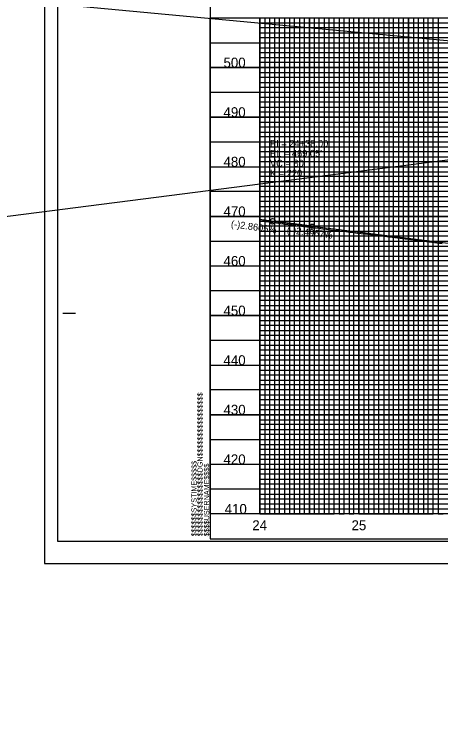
# Model space of a CAD drawing. Extents: x 571503 to 593215, y -77195 to -51828.
# Drawn here: x 581475 to 581905, y -53851 to -53130 of the extents above; entities that cross this region are included whole.
import ezdxf

# ---------------------------------------------------------------- set-up
doc = ezdxf.new("R2010")
doc.units = 0
for name, color, linetype in [('Default', 7, 'Continuous'), ('Exist Vertical Profile Ground Line', 7, 'Continuous'), ('Exist Vertical Profile Horizontal Axis Label Major', 7, 'Continuous'), ('Exist Vertical Profile Vertical Axis Label', 7, 'Continuous'), ('Prop PFL Text', 7, 'Continuous'), ('Prop Vertical Profile Curve Label', 7, 'Continuous'), ('Prop Vertical Profile Grade', 7, 'Continuous'), ('Prop Vertical Profile Grade Label', 7, 'Continuous'), ('Prop VPI Label', 7, 'Continuous'), ('Sheet Clip Boundary CELL', 7, 'Continuous'), ('Sheet DOT Grid CELL', 7, 'Continuous'), ('Sheet Plot Border Inside CELL', 7, 'Continuous'), ('Sheet Plot Border Outside CELL', 7, 'Continuous'), ('Sheet Profile CELL', 7, 'Continuous'), ('Sheet Profile Grid Major CELL', 7, 'Continuous'), ('Sheet Profile Grid Middle CELL', 7, 'Continuous'), ('Sheet Profile Grid Minor CELL', 7, 'Continuous')]:
    doc.layers.add(name, color=color, linetype=linetype)

msp = doc.modelspace()

# ---------------------------------------------------------------- linework, layer by layer
at = {"layer": 'Default'}
msp.add_line((581722.51, -53633.7), (581672.51, -53633.7), dxfattribs=at)
at = {"layer": 'Exist Vertical Profile Ground Line'}
msp.add_lwpolyline([(581722.51, -53338.07), (581727.78, -53338.78), (581731.67, -53339.31), (581735.55, -53339.84), (581739.44, -53340.37), (581743.32, -53340.9), (581746.1, -53341.28), (581747.21, -53341.43), (581747.83, -53341.52), (581751.09, -53341.92), (581754.97, -53342.39), (581758.86, -53342.87), (581762.74, -53343.34), (581766.63, -53343.81), (581768.43, -53344.03), (581770.12, -53344.26), (581770.51, -53344.31), (581774.4, -53344.78), (581778.28, -53345.26), (581782.16, -53345.73), (581786.05, -53346.21), (581789.93, -53346.68), (581793.82, -53347.15), (581797.7, -53347.63), (581800.14, -53347.93), (581801.59, -53348.12), (581801.83, -53348.15), (581805.47, -53348.6), (581809.35, -53349.07), (581813.24, -53349.55), (581817.12, -53350.02), (581821.01, -53350.5), (581821.09, -53350.51), (581821.15, -53350.52), (581822.44, -53350.66), (581824.89, -53350.96), (581828.78, -53351.44), (581853.26, -53354.42), (581853.28, -53354.42), (581874.55, -53357.06), (581874.95, -53357.11), (581906.3, -53361)], dxfattribs=at)
at = {"layer": 'Prop PFL Text'}
for p, q in [((571799.62, -54572.45), (593215.36, -51828.37)), ((571620.66, -52186.29), (592499.52, -54154.87))]:
    msp.add_line(p, q, dxfattribs=at)
at = {"layer": 'Prop Vertical Profile Curve Label'}
msp.add_circle((581775.51, -53343.69), 2.25, dxfattribs=at)
at = {"layer": 'Prop Vertical Profile Grade'}
msp.add_line((581775.51, -53343.69), (581918.01, -53361.48), dxfattribs=at)
msp.add_spline([(581722.68, -53336.78), (581722.71, -53336.78), (581724.31, -53337), (581725.91, -53337.22), (581727.51, -53337.44), (581729.11, -53337.66), (581730.71, -53337.87), (581732.31, -53338.09), (581733.91, -53338.3), (581735.51, -53338.52), (581737.11, -53338.73), (581738.71, -53338.95), (581740.31, -53339.16), (581741.91, -53339.37), (581743.51, -53339.58), (581745.11, -53339.79), (581746.71, -53340), (581748.31, -53340.21), (581749.91, -53340.42), (581751.51, -53340.63), (581753.11, -53340.84), (581754.71, -53341.05), (581756.31, -53341.25), (581757.91, -53341.46), (581759.51, -53341.67), (581761.11, -53341.87), (581762.71, -53342.08), (581764.31, -53342.28), (581765.91, -53342.48), (581767.51, -53342.69), (581769.11, -53342.89), (581770.71, -53343.09), (581772.31, -53343.29), (581773.91, -53343.49), (581775.51, -53343.69)], degree=3, dxfattribs=at)
at = {"layer": 'Prop VPI Label'}
for p, q in [((581722.51, -53336.84), (581732.79, -53338.31)), ((581775.51, -53343.69), (581738.24, -53339.04))]:
    msp.add_line(p, q, dxfattribs=at)
msp.add_circle((581735.51, -53338.7), 2.75, dxfattribs=at)
at = {"layer": 'Sheet Clip Boundary CELL'}
msp.add_lwpolyline([(581722.51, -53133.7), (583122.51, -53133.7), (583122.51, -53633.7), (581722.51, -53633.7)], close=True, dxfattribs=at)
at = {"layer": 'Sheet DOT Grid CELL'}
for p, q in [((581672.51, -53633.7), (581672.51, -53133.7)), ((581672.51, -53133.7), (583172.39, -53133.7)), ((581722.51, -53633.7), (581722.51, -53133.7)), ((581722.51, -53133.7), (581722.51, -53633.7)), ((581772.51, -53633.7), (581772.51, -53133.7)), ((581772.51, -53133.7), (581772.51, -53633.7)), ((581822.51, -53633.7), (581822.51, -53133.7)), ((581822.51, -53133.7), (581822.51, -53633.7)), ((581872.51, -53633.7), (581872.51, -53133.7)), ((581872.51, -53133.7), (581872.51, -53633.7)), ((581672.51, -53183.7), (583172.51, -53183.7)), ((581672.51, -53183.7), (583172.39, -53183.7)), ((581672.51, -53233.7), (583172.51, -53233.7)), ((581672.51, -53233.7), (583172.39, -53233.7)), ((581672.51, -53283.7), (583172.51, -53283.7)), ((581672.51, -53283.7), (583172.39, -53283.7)), ((581672.51, -53333.7), (583172.51, -53333.7)), ((581672.51, -53333.7), (583172.39, -53333.7)), ((581672.51, -53383.7), (583172.51, -53383.7)), ((581672.51, -53383.7), (583172.39, -53383.7)), ((581672.51, -53433.7), (583172.51, -53433.7)), ((581672.51, -53433.7), (583172.39, -53433.7)), ((581672.51, -53483.7), (583172.51, -53483.7)), ((581672.51, -53483.7), (583172.39, -53483.7)), ((581672.51, -53533.7), (583172.51, -53533.7)), ((581672.51, -53533.7), (583172.39, -53533.7)), ((581672.51, -53583.7), (583172.51, -53583.7)), ((581672.51, -53583.7), (583172.39, -53583.7))]:
    msp.add_line(p, q, dxfattribs=at)
at = {"layer": 'Sheet Plot Border Inside CELL'}
msp.add_lwpolyline([(581518.51, -53661.25), (583185.01, -53661.25), (583185.01, -52606.15), (581518.51, -52606.15)], close=True, dxfattribs=at)
at = {"layer": 'Sheet Plot Border Outside CELL'}
msp.add_lwpolyline([(581505.51, -53683.7), (583189.51, -53683.7), (583189.51, -52583.7), (581505.51, -52583.7)], close=True, dxfattribs=at)
at = {"layer": 'Sheet Profile CELL'}
for p, q in [((581505.51, -52583.7), (581505.51, -53683.7)), ((581672.51, -53133.7), (583172.51, -53133.7)), ((581524.01, -53431.2), (581536.51, -53431.2)), ((583172.51, -53633.7), (581672.51, -53633.7)), ((581672.51, -53658.7), (583172.51, -53658.7)), ((581672.51, -53658.7), (581672.51, -53658.7)), ((581672.51, -53658.7), (581672.51, -53658.7)), ((581672.51, -53658.7), (581672.51, -53658.7)), ((581672.51, -53658.7), (581672.51, -53658.7)), ((581672.51, -53658.7), (581672.51, -53658.7)), ((581672.51, -53658.7), (581672.51, -53658.7)), ((581672.51, -53658.7), (581672.51, -53658.7)), ((581505.51, -53683.7), (583189.51, -53683.7))]:
    msp.add_line(p, q, dxfattribs=at)
msp.add_lwpolyline([(583172.51, -52608.7), (581672.51, -52608.7), (581672.51, -53658.7), (583172.51, -53658.7)], close=True, dxfattribs=at)
msp.add_lwpolyline([(581710.01, -53658.7), (581710.01, -53658.7)], dxfattribs=at)
at = {"layer": 'Sheet Profile Grid Major CELL'}
msp.add_line((581672.51, -53633.7), (581672.51, -53633.7), dxfattribs=at)
for points in [[(581722.51, -53133.7), (581722.51, -53633.7), (581772.51, -53633.7), (581772.51, -53133.7), (581822.51, -53133.7), (581822.51, -53633.7), (581872.51, -53633.7), (581872.51, -53133.7), (581922.51, -53133.7)], [(583172.51, -53183.7), (581672.51, -53183.7)], [(583172.51, -53233.7), (581672.51, -53233.7), (581672.51, -53283.7), (583172.51, -53283.7)], [(583172.51, -53333.7), (581672.51, -53333.7), (581672.51, -53383.7), (583172.51, -53383.7)], [(583172.51, -53433.7), (581672.51, -53433.7), (581672.51, -53483.7), (583172.51, -53483.7)], [(583172.51, -53533.7), (581672.51, -53533.7), (581672.51, -53533.7), (581672.51, -53583.7), (583172.51, -53583.7)], [(583172.51, -53633.7), (581672.51, -53633.7)]]:
    msp.add_lwpolyline(points, dxfattribs=at)
at = {"layer": 'Sheet Profile Grid Middle CELL'}
for points in [[(581697.51, -53133.7), (581747.51, -53133.7), (581747.51, -53633.7), (581797.51, -53633.7), (581797.51, -53133.7), (581847.51, -53133.7), (581847.51, -53633.7), (581897.51, -53633.7), (581897.51, -53133.7), (581947.51, -53133.7)], [(581672.51, -53158.7), (583172.51, -53158.7)], [(583172.51, -53208.7), (581672.51, -53208.7), (581672.51, -53258.7), (583172.51, -53258.7)], [(583172.51, -53308.7), (581672.51, -53308.7), (581672.51, -53358.7), (583172.51, -53358.7)], [(583172.51, -53408.7), (581672.51, -53408.7), (581672.51, -53458.7), (583172.51, -53458.7)], [(583172.51, -53508.7), (581672.51, -53508.7), (581672.51, -53558.7), (583172.51, -53558.7)], [(583172.51, -53608.7), (581672.51, -53608.7)]]:
    msp.add_lwpolyline(points, dxfattribs=at)
at = {"layer": 'Sheet Profile Grid Minor CELL'}
for p, q in [((581722.51, -53138.7), (583122.51, -53138.7)), ((583122.51, -53143.7), (581722.51, -53143.7)), ((581722.51, -53148.7), (583122.51, -53148.7)), ((583122.51, -53153.7), (581722.51, -53153.7)), ((581722.51, -53163.7), (583122.51, -53163.7)), ((583122.51, -53168.7), (581722.51, -53168.7)), ((581722.51, -53173.7), (583122.51, -53173.7)), ((583122.51, -53178.7), (581722.51, -53178.7)), ((581722.51, -53188.7), (583122.51, -53188.7)), ((583122.51, -53193.7), (581722.51, -53193.7)), ((581722.51, -53198.7), (583122.51, -53198.7)), ((583122.51, -53203.7), (581722.51, -53203.7)), ((581722.51, -53213.7), (583122.51, -53213.7)), ((583122.51, -53218.7), (581722.51, -53218.7)), ((581722.51, -53223.7), (583122.51, -53223.7)), ((583122.51, -53228.7), (581722.51, -53228.7)), ((581722.51, -53238.7), (583122.51, -53238.7)), ((583122.51, -53243.7), (581722.51, -53243.7)), ((581722.51, -53248.7), (583122.51, -53248.7)), ((583122.51, -53253.7), (581722.51, -53253.7)), ((581722.51, -53263.7), (583122.51, -53263.7)), ((583122.51, -53268.7), (581722.51, -53268.7)), ((581722.51, -53273.7), (583122.51, -53273.7)), ((583122.51, -53278.7), (581722.51, -53278.7)), ((581722.51, -53288.7), (583122.51, -53288.7)), ((583122.51, -53293.7), (581722.51, -53293.7)), ((581722.51, -53298.7), (583122.51, -53298.7)), ((583122.51, -53303.7), (581722.51, -53303.7)), ((581722.51, -53313.7), (583122.51, -53313.7)), ((583122.51, -53318.7), (581722.51, -53318.7)), ((581722.51, -53323.7), (583122.51, -53323.7)), ((583122.51, -53328.7), (581722.51, -53328.55)), ((581722.51, -53338.7), (583122.51, -53338.7)), ((583122.51, -53343.7), (581722.51, -53343.7)), ((581722.51, -53348.7), (583122.51, -53348.7)), ((583122.51, -53353.7), (581722.51, -53353.7)), ((581722.51, -53363.7), (583122.51, -53363.7)), ((583122.51, -53368.7), (581722.51, -53368.7)), ((581722.51, -53373.7), (583122.51, -53373.7)), ((583122.51, -53378.7), (581722.51, -53378.7)), ((581722.51, -53388.7), (583122.51, -53388.7)), ((583122.51, -53393.7), (581722.51, -53393.7)), ((581722.51, -53398.7), (583122.51, -53398.7)), ((583122.51, -53403.7), (581722.51, -53403.7)), ((581722.51, -53413.7), (583122.51, -53413.7)), ((583122.51, -53418.7), (581722.51, -53418.7)), ((581722.51, -53423.7), (583122.51, -53423.7)), ((583122.51, -53428.7), (581722.51, -53428.7)), ((581722.51, -53438.7), (583122.51, -53438.7)), ((583122.51, -53443.7), (581722.51, -53443.7)), ((581722.51, -53448.7), (583122.51, -53448.7)), ((583122.51, -53453.7), (581722.51, -53453.7)), ((581722.51, -53463.7), (583122.51, -53463.7)), ((583122.51, -53468.7), (581722.51, -53468.7)), ((581722.51, -53473.7), (583122.51, -53473.7)), ((583122.51, -53478.7), (581722.51, -53478.7)), ((581722.51, -53488.7), (583122.51, -53488.7)), ((583122.51, -53493.7), (581722.51, -53493.7)), ((581722.51, -53498.7), (583122.51, -53498.7)), ((583122.51, -53503.7), (581722.51, -53503.7)), ((581722.51, -53513.7), (583122.51, -53513.7)), ((583122.51, -53518.7), (581722.51, -53518.7)), ((581722.51, -53523.7), (583122.51, -53523.7)), ((583122.51, -53528.7), (581722.51, -53528.7)), ((581722.51, -53538.7), (583122.51, -53538.7)), ((583122.51, -53543.7), (581722.51, -53543.7)), ((581722.51, -53548.7), (583122.51, -53548.7)), ((583122.51, -53553.7), (581722.51, -53553.7)), ((581722.51, -53563.7), (583122.51, -53563.7)), ((583122.51, -53568.7), (581722.51, -53568.7)), ((581722.51, -53573.7), (583122.51, -53573.7)), ((583122.51, -53578.7), (581722.51, -53578.7)), ((581722.51, -53588.7), (583122.51, -53588.7)), ((583122.51, -53593.7), (581722.51, -53593.7)), ((581722.51, -53598.7), (583122.51, -53598.7)), ((583122.51, -53603.7), (581722.51, -53603.7)), ((581722.51, -53613.7), (583122.51, -53613.7)), ((583122.51, -53618.7), (581722.51, -53618.7)), ((581722.51, -53623.7), (583122.51, -53623.7)), ((581722.51, -53628.7), (583122.51, -53628.7))]:
    msp.add_line(p, q, dxfattribs=at)
for points in [[(581722.51, -53133.7), (581727.51, -53133.7), (581727.51, -53633.7), (581732.51, -53633.7), (581732.51, -53133.7), (581737.51, -53133.7), (581737.51, -53633.7), (581742.51, -53633.7), (581742.51, -53133.7), (581752.51, -53133.7), (581752.51, -53633.7), (581757.51, -53633.7), (581757.51, -53133.7), (581762.51, -53133.7), (581762.51, -53633.7), (581767.51, -53633.7), (581777.51, -53633.7), (581782.51, -53633.7), (581782.51, -53133.7), (581787.51, -53133.7), (581787.51, -53633.7), (581792.51, -53633.7), (581792.51, -53133.7), (581802.51, -53133.7), (581802.51, -53633.7), (581807.51, -53633.7), (581807.51, -53133.7), (581812.51, -53133.7), (581812.51, -53633.7), (581817.51, -53633.7), (581817.51, -53133.7), (581827.51, -53133.7), (581827.51, -53633.7), (581832.51, -53633.7), (581832.51, -53133.7), (581837.51, -53133.7), (581837.51, -53633.7), (581842.51, -53633.7), (581842.51, -53133.7), (581852.51, -53133.7), (581852.51, -53633.7), (581857.51, -53633.7), (581857.51, -53133.7), (581862.51, -53133.7), (581862.51, -53633.7), (581867.51, -53633.7), (581867.51, -53133.7), (581877.51, -53133.7), (581877.51, -53633.7), (581882.51, -53633.7), (581882.51, -53133.7), (581887.51, -53133.7), (581887.51, -53633.7), (581892.51, -53633.7), (581892.51, -53133.7), (581902.51, -53133.7), (581902.51, -53633.7), (581907.51, -53633.7)], [(581767.51, -53633.7), (581767.51, -53133.7), (581777.51, -53133.7), (581777.51, -53633.7)]]:
    msp.add_lwpolyline(points, dxfattribs=at)

# ---------------------------------------------------------------- texts
at = {"layer": 'Exist Vertical Profile Horizontal Axis Label Major'}
for s, p in [('24', (581714.96, -53650.13)), ('25', (581815.05, -53650.13))]:
    msp.add_text(s, height=10, dxfattribs=at).set_placement(p)
at = {"layer": 'Exist Vertical Profile Vertical Axis Label'}
for s, p in [('500', (581685.94, -53183.7)), ('500', (581685.94, -53183.7)), ('490', (581685.94, -53233.7)), ('490', (581685.94, -53233.7)), ('480', (581685.94, -53283.7)), ('480', (581685.94, -53283.7)), ('470', (581685.94, -53333.7)), ('470', (581685.94, -53333.7)), ('460', (581685.94, -53383.7)), ('460', (581685.94, -53383.7)), ('450', (581685.94, -53433.7)), ('450', (581685.94, -53433.7)), ('440', (581685.94, -53483.7)), ('440', (581685.94, -53483.7)), ('430', (581685.94, -53533.7)), ('430', (581685.94, -53533.7)), ('420', (581685.94, -53583.7)), ('420', (581685.94, -53583.7)), ('410', (581687.14, -53633.7)), ('410', (581687.14, -53633.7))]:
    msp.add_text(s, height=10, dxfattribs=at).set_placement(p)
at = {"layer": 'Prop Vertical Profile Curve Label'}
for s, p in [("VC = 80'", (581732.79, -53283.7)), ('K = 220', (581732.79, -53293.63))]:
    msp.add_text(s, height=7, dxfattribs=at).set_placement(p)
at = {"layer": 'Prop Vertical Profile Grade Label'}
for s, rotation, p in [('(-)2.8605%', 351.86057, (581693.13, -53344.49)), ('(-)2.4967%', 352.88439, (581749.57, -53350.53))]:
    msp.add_text(s, height=7, rotation=rotation, dxfattribs=at).set_placement(p)
at = {"layer": 'Prop VPI Label'}
for s, p in [('PI = 24+38.00', (581732.79, -53263.7)), ("EL = 469.05'", (581732.79, -53273.7))]:
    msp.add_text(s, height=7, dxfattribs=at).set_placement(p)
at = {"layer": 'Sheet Profile CELL'}
for s, p in [('$$$$$$$$$$$$$$$$DGN$$$$$$$$$$$$$$$$', (581664.87, -53656.32)), ('$$$$$$SYSTIME$$$$$', (581658.82, -53656.32)), ('$$$$USERNAME$$$$', (581671.45, -53656.31))]:
    msp.add_text(s, height=5.25, rotation=90, dxfattribs=at).set_placement(p)

doc.saveas('drawing.dxf')
